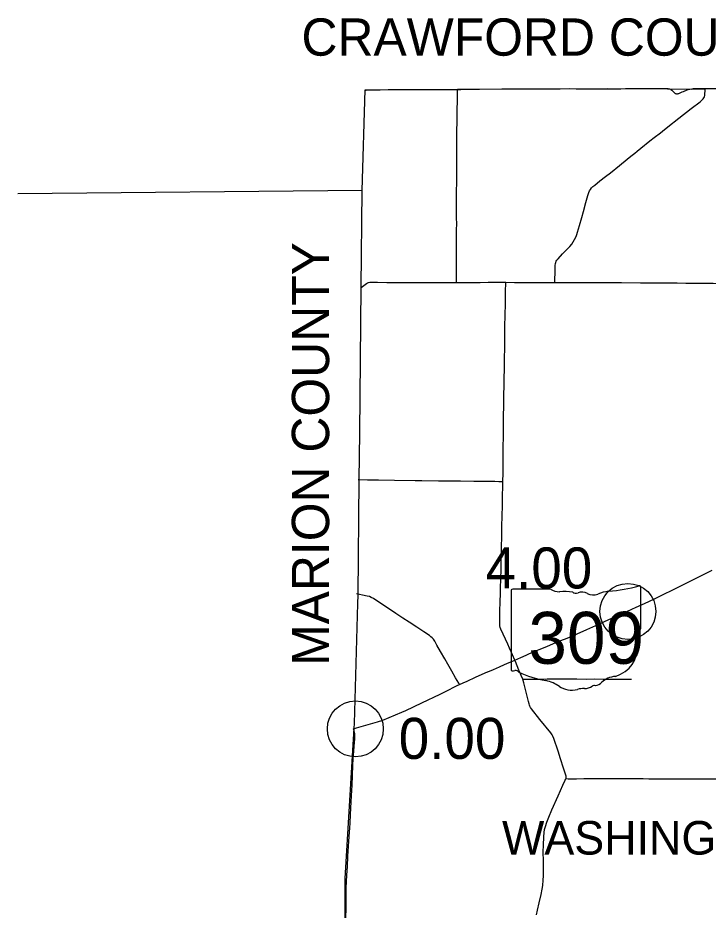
# Model space of a CAD drawing. Extents: x 1813937 to 1948437, y 826606 to 1022856.
# Drawn here: x 1859869 to 1878388, y 966228 to 990160 of the extents above; entities that cross this region are included whole.
import ezdxf

# ---------------------------------------------------------------- set-up
doc = ezdxf.new("R2010")
doc.units = 0
for name, color, linetype in [('Default', 7, 'Continuous'), ('GM_X_Adjacent_County', 7, 'Continuous'), ('GM_X_Adjacent_County_Text', 7, 'Continuous'), ('GM_X_County', 7, 'Continuous'), ('GM_X_County_Road', 7, 'Continuous'), ('GM_X_State_Route', 7, 'Continuous'), ('GM_X_State_Shield', 7, 'Continuous'), ('GM_X_Township_Road', 7, 'Continuous'), ('GM_X_Township_Text', 7, 'Continuous')]:
    doc.layers.add(name, color=color, linetype=linetype)

msp = doc.modelspace()

# ---------------------------------------------------------------- linework, layer by layer
at = {"layer": 'Default'}
for centre in [(1876236, 974240), (1868924, 971089)]:
    msp.add_circle(centre, 750, dxfattribs=at)
at = {"layer": 'GM_X_Adjacent_County'}
msp.add_line((1869110, 985528), (1859869, 985436), dxfattribs=at)
at = {"layer": 'GM_X_County'}
msp.add_lwpolyline([(1868643, 964155), (1868654, 967077), (1868896, 971111), (1868903, 971230), (1868993, 974454), (1868995, 974673), (1869028, 977767), (1869041, 979034), (1869083, 982941), (1869110, 985528), (1869183, 988230), (1871661, 988243), (1875677, 988261), (1877300, 988258), (1877944, 988247), (1878309, 988257), (1879625, 988278)], dxfattribs=at)
at = {"layer": 'GM_X_County_Road'}
for points in [[(1869191, 988216), (1869213, 988220), (1869245, 988225), (1869294, 988229), (1869376, 988231), (1869590, 988232), (1869803, 988236), (1870051, 988238), (1870416, 988241), (1870657, 988241), (1870838, 988241), (1871018, 988242), (1871297, 988242), (1871577, 988242), (1871661, 988242)], [(1871661, 988242), (1871757, 988241), (1871923, 988244), (1872250, 988251), (1872857, 988256), (1873350, 988258), (1873629, 988258), (1873925, 988259), (1874253, 988259), (1874417, 988258), (1874663, 988261), (1874844, 988260), (1875139, 988257), (1875402, 988259), (1875632, 988258), (1875672, 988258)], [(1875672, 988258), (1875796, 988259), (1876042, 988260), (1876174, 988261), (1876404, 988261), (1876617, 988261), (1876880, 988261), (1877143, 988262), (1877257, 988263)], [(1869076, 982927), (1869218, 983033), (1869246, 983050), (1869276, 983063), (1869308, 983071), (1869340, 983074), (1869406, 983072), (1869520, 983067), (1869766, 983066), (1870209, 983065), (1870685, 983065), (1871390, 983066), (1871633, 983066)], [(1871633, 983066), (1871767, 983066), (1872276, 983066), (1872489, 983068), (1872915, 983067), (1872959, 983067)], [(1872883, 977728), (1872885, 977952), (1872887, 978231), (1872890, 978559), (1872895, 979018), (1872900, 979346), (1872916, 980444), (1872921, 980789), (1872925, 981002), (1872930, 981330), (1872932, 981494), (1872936, 981707), (1872938, 981870), (1872943, 982198), (1872947, 982477), (1872954, 982854), (1872958, 983018), (1872958, 983035), (1872959, 983067)], [(1872959, 983067), (1873193, 983066), (1873489, 983064), (1873899, 983064), (1874243, 983063), (1874277, 983063)], [(1874277, 983063), (1874390, 983063), (1874964, 983063), (1875374, 983063), (1875702, 983061), (1876063, 983060), (1876572, 983057), (1877195, 983051), (1877555, 983049), (1877785, 983048), (1877916, 983047), (1878293, 983044), (1878523, 983041), (1878998, 983036), (1879326, 983034), (1879572, 983030), (1879834, 983026), (1880113, 983025), (1880309, 983024), (1880352, 983024), (1880363, 983024)], [(1872832, 975375), (1872836, 975482), (1872839, 975662), (1872842, 975776), (1872844, 975874), (1872845, 975923), (1872846, 975942), (1872846, 975974), (1872847, 976021), (1872850, 976200), (1872854, 976461), (1872863, 976855), (1872867, 977018), (1872874, 977280), (1872883, 977657), (1872883, 977728)], [(1873200, 972935), (1873141, 973076), (1873061, 973256), (1873013, 973359), (1872951, 973493), (1872825, 973760), (1872808, 973807), (1872799, 973856), (1872795, 973922), (1872797, 974035), (1872797, 974070), (1872802, 974233), (1872811, 974511), (1872816, 974707), (1872821, 974871), (1872828, 975101), (1872832, 975375)], [(1873262, 972784), (1873217, 972895), (1873200, 972935)], [(1873329, 972626), (1873310, 972668), (1873262, 972784)], [(1873414, 972427), (1873374, 972525), (1873329, 972626)], [(1873498, 972111), (1873444, 972329), (1873415, 972423), (1873414, 972427)], [(1873592, 971723), (1873582, 971760), (1873567, 971821), (1873507, 972075), (1873498, 972111)], [(1874573, 969761), (1874576, 969771), (1874579, 969786), (1874579, 969801), (1874575, 969822), (1874568, 969848), (1874509, 970035), (1874428, 970285), (1874361, 970488), (1874249, 970830), (1874225, 970891), (1874202, 970933), (1874164, 970986), (1873875, 971343), (1873650, 971625), (1873621, 971666), (1873605, 971695), (1873592, 971723)], [(1873787, 966104), (1873814, 966232), (1873858, 966424), (1873909, 966648), (1873937, 966793), (1873951, 966890), (1873965, 967036), (1873971, 967151), (1873972, 967265), (1873967, 967544), (1873963, 967789), (1873967, 967970), (1873978, 968199), (1873989, 968314), (1874002, 968395), (1874022, 968475), (1874057, 968585), (1874111, 968722), (1874195, 968918), (1874362, 969293), (1874489, 969577), (1874550, 969711), (1874570, 969756), (1874573, 969761)], [(1874573, 969761), (1874584, 969760), (1874629, 969754), (1874713, 969754), (1874860, 969754), (1875057, 969756), (1875204, 969756), (1875417, 969757), (1875974, 969755), (1876187, 969755), (1876465, 969756), (1876645, 969755), (1876793, 969753), (1877038, 969751), (1877186, 969750), (1877448, 969749), (1877890, 969747), (1878250, 969746), (1878610, 969747), (1879069, 969749), (1879220, 969750)]]:
    msp.add_lwpolyline(points, dxfattribs=at)
at = {"layer": 'GM_X_State_Route'}
for points in [[(1876453, 974353), (1876683, 974457), (1876950, 974582), (1877201, 974705), (1877421, 974814), (1877995, 975098), (1878334, 975264), (1878495, 975346)], [(1873856, 973217), (1874061, 973302), (1874242, 973380), (1874328, 973413), (1874435, 973456), (1874603, 973525), (1874875, 973639), (1875131, 973751), (1875459, 973900), (1875727, 974024), (1876087, 974185), (1876340, 974301), (1876453, 974353)], [(1871338, 972094), (1871654, 972249), (1871717, 972279), (1871817, 972327), (1871922, 972374), (1872146, 972475), (1872326, 972554), (1872469, 972616), (1872476, 972620), (1872631, 972687), (1872790, 972756), (1872807, 972764), (1873002, 972849), (1873123, 972901), (1873200, 972935), (1873363, 973008), (1873502, 973068), (1873573, 973099), (1873686, 973147), (1873708, 973156), (1873765, 973179), (1873807, 973197), (1873856, 973217)], [(1870169, 971540), (1870279, 971587), (1870709, 971792), (1871197, 972025), (1871338, 972094)], [(1868870, 971092), (1868952, 971118), (1869208, 971190), (1869518, 971281), (1869659, 971326), (1870169, 971540)]]:
    msp.add_lwpolyline(points, dxfattribs=at)
at = {"layer": 'GM_X_State_Shield'}
for p, q in [((1873100, 974800), (1873100, 972687)), ((1874154, 974836), (1873135, 974836)), ((1876581, 973783), (1876581, 974889)), ((1876580, 973783), (1876581, 973783))]:
    msp.add_line(p, q, dxfattribs=at)
for centre, major_axis, start_param, end_param in [((1873140, 974804), (40.3, 0), 1.712693, 3.28349), ((1874397, 975082), (391, 0), 4.042523, 4.731795), ((1874526, 973650), (1404, 0), 1.404758, 1.657858), ((1874845, 974815), (113, 0), 3.836095, 5.185415), ((1875011, 974571), (235, 0), 0.950623, 2.079405), ((1875812, 974191), (743, 0), 1.699011, 2.107814), ((1875341, 977717), (3691, 0), 4.814394, 5.042369), ((1876542, 974893), (38.7, 0), 6.141152, 7.989035), ((1875313, 974906), (282, 0), 4.081561, 5.145723), ((1876539, 973779), (41.5, 0), 5.05454, 6.418171), ((1876572, 973702), (60, 0), 1.883978, 3.671073), ((1876190, 973562), (360, 0), 5.934695, 6.695948), ((1875548, 973180), (923, 0), 5.101752, 6.440018), ((1876720, 973321), (262, 0), 2.387724, 3.262537), ((1873141, 972682), (40.7, 0), 3.00124, 4.508301), ((1873147, 972898), (310, 0), 4.665946, 4.897461), ((1873210, 972565), (112, 0), 0.519207, 1.627899), ((1874623, 974463), (2665, 0), 4.195997, 4.488961), ((1873829, 971737), (834, 0), 0.823519, 1.323587), ((1875296, 972482), (298, 0), 4.937069, 5.64225), ((1875937, 972093), (506, 0), 1.647645, 2.488434), ((1874731, 972554), (529, 0), 4.026481, 4.996735), ((1875037, 971824), (435, 0), 1.495662, 1.94098), ((1875075, 972396), (282, 0), 4.691044, 5.507374), ((1875330, 972191), (79.4, 0), 1.147584, 2.315152)]:
    msp.add_ellipse(centre, major_axis=major_axis, ratio=0.8, start_param=start_param, end_param=end_param, dxfattribs=at)
at = {"layer": 'GM_X_Township_Road'}
for points in [[(1871633, 983066), (1871633, 983101), (1871633, 983347), (1871636, 983986), (1871640, 984445), (1871642, 984658), (1871640, 984773), (1871638, 984953), (1871640, 985314), (1871643, 985937), (1871648, 986478), (1871650, 987003), (1871654, 987495), (1871660, 988135), (1871661, 988216), (1871661, 988242)], [(1876419, 986529), (1876483, 986580), (1876585, 986662), (1876827, 986858), (1876942, 986950), (1877110, 987080), (1877162, 987121), (1877302, 987234), (1877599, 987467), (1877936, 987727), (1878170, 987907), (1878220, 987949), (1878254, 987985), (1878272, 988012), (1878286, 988042), (1878296, 988073), (1878301, 988105), (1878306, 988220), (1878305, 988238), (1878304, 988253), (1878301, 988267)], [(1877257, 988263), (1877303, 988261), (1877325, 988258), (1877350, 988253), (1877377, 988243), (1877390, 988236), (1877413, 988218), (1877468, 988164), (1877493, 988143), (1877506, 988134), (1877520, 988127), (1877536, 988123), (1877552, 988123), (1877568, 988126), (1877583, 988130), (1877599, 988135), (1877691, 988171), (1877723, 988184), (1877829, 988225), (1877852, 988234), (1877901, 988248), (1877946, 988257)], [(1877946, 988257), (1877965, 988260), (1877973, 988260), (1877996, 988262), (1878029, 988264)], [(1878029, 988264), (1878045, 988265), (1878127, 988265), (1878301, 988267)], [(1878301, 988267), (1878457, 988268), (1878956, 988279), (1879160, 988283), (1879620, 988289)], [(1874277, 983063), (1874277, 983094), (1874280, 983373), (1874283, 983521), (1874290, 983569), (1874299, 983600), (1874313, 983630), (1874330, 983658), (1874361, 983696), (1874485, 983827), (1874677, 984030), (1874729, 984093), (1874765, 984148), (1874806, 984218), (1874843, 984292), (1874868, 984352), (1874887, 984415), (1874934, 984589), (1874998, 984809), (1875043, 984967), (1875108, 985204), (1875160, 985394), (1875186, 985472), (1875206, 985517), (1875231, 985559), (1875260, 985598), (1875294, 985634), (1875344, 985676), (1875486, 985787), (1875638, 985905), (1875765, 986007), (1876008, 986202), (1876213, 986366), (1876315, 986448), (1876419, 986529)], [(1869001, 977778), (1869250, 977773), (1869546, 977769), (1869972, 977762), (1870529, 977753), (1870709, 977751), (1871152, 977746), (1871743, 977739), (1872103, 977737), (1872399, 977733), (1872661, 977730), (1872775, 977729), (1872857, 977728), (1872883, 977728)], [(1871614, 972458), (1871510, 972641), (1871404, 972827), (1871321, 972968), (1871207, 973167), (1871110, 973339), (1871054, 973439), (1871018, 973492), (1870986, 973529), (1870951, 973563), (1870913, 973593), (1870763, 973693), (1870570, 973818), (1870364, 973953), (1870199, 974060), (1870007, 974186), (1869789, 974332), (1869611, 974449), (1869406, 974586), (1869350, 974618), (1869305, 974637), (1869243, 974653), (1869114, 974678), (1868957, 974709)], [(1871717, 972279), (1871697, 972314), (1871614, 972458)], [(1873414, 972427), (1873446, 972427), (1873615, 972427)], [(1873615, 972427), (1873760, 972427)], [(1873760, 972427), (1873857, 972427), (1874066, 972431), (1874329, 972431), (1874723, 972429), (1874868, 972429), (1875129, 972426), (1875326, 972430), (1875572, 972427), (1875983, 972421), (1876164, 972421), (1876295, 972424), (1876328, 972425)], [(1868668, 965744), (1868676, 966548), (1868681, 966827), (1868697, 967171), (1868710, 967400), (1868725, 967679), (1868732, 967810), (1868757, 968203), (1868771, 968432), (1868780, 968563), (1868794, 968792), (1868822, 969300), (1868834, 969579), (1868845, 969841), (1868860, 970120), (1868867, 970284), (1868883, 970496), (1868894, 970626), (1868908, 970823), (1868910, 970905), (1868906, 970955), (1868897, 971004), (1868888, 971037), (1868870, 971092)]]:
    msp.add_lwpolyline(points, dxfattribs=at)

# ---------------------------------------------------------------- texts
at = {"layer": 'Default'}
for s, p in [('4.00', (1872417, 974856)), ('0.00', (1870086, 970285))]:
    msp.add_text(s, height=1100, dxfattribs=at).set_placement(p)
at = {"layer": 'GM_X_Adjacent_County_Text'}
msp.add_text('CRAWFORD COUNTY', height=1000, dxfattribs=at).set_placement((1867478, 989145))
msp.add_text('MARION COUNTY', height=1000, rotation=90, dxfattribs=at).set_placement((1868220, 972779))
at = {"layer": 'GM_X_State_Shield'}
msp.add_text('309', height=1392.2, dxfattribs=at).set_placement((1873564, 972836))
at = {"layer": 'GM_X_Township_Text'}
msp.add_text('WASHINGTON', height=900, rotation=0, dxfattribs=at).set_placement((1872858, 967719))

doc.saveas('drawing.dxf')
